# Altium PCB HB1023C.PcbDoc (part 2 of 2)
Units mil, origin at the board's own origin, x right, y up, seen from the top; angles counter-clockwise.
Board outline 1895.03 x 2760.94 mil, 2 copper layers (Top Layer, Bottom Layer); 83 components, 64 nets, 266 pads, 261 vias.
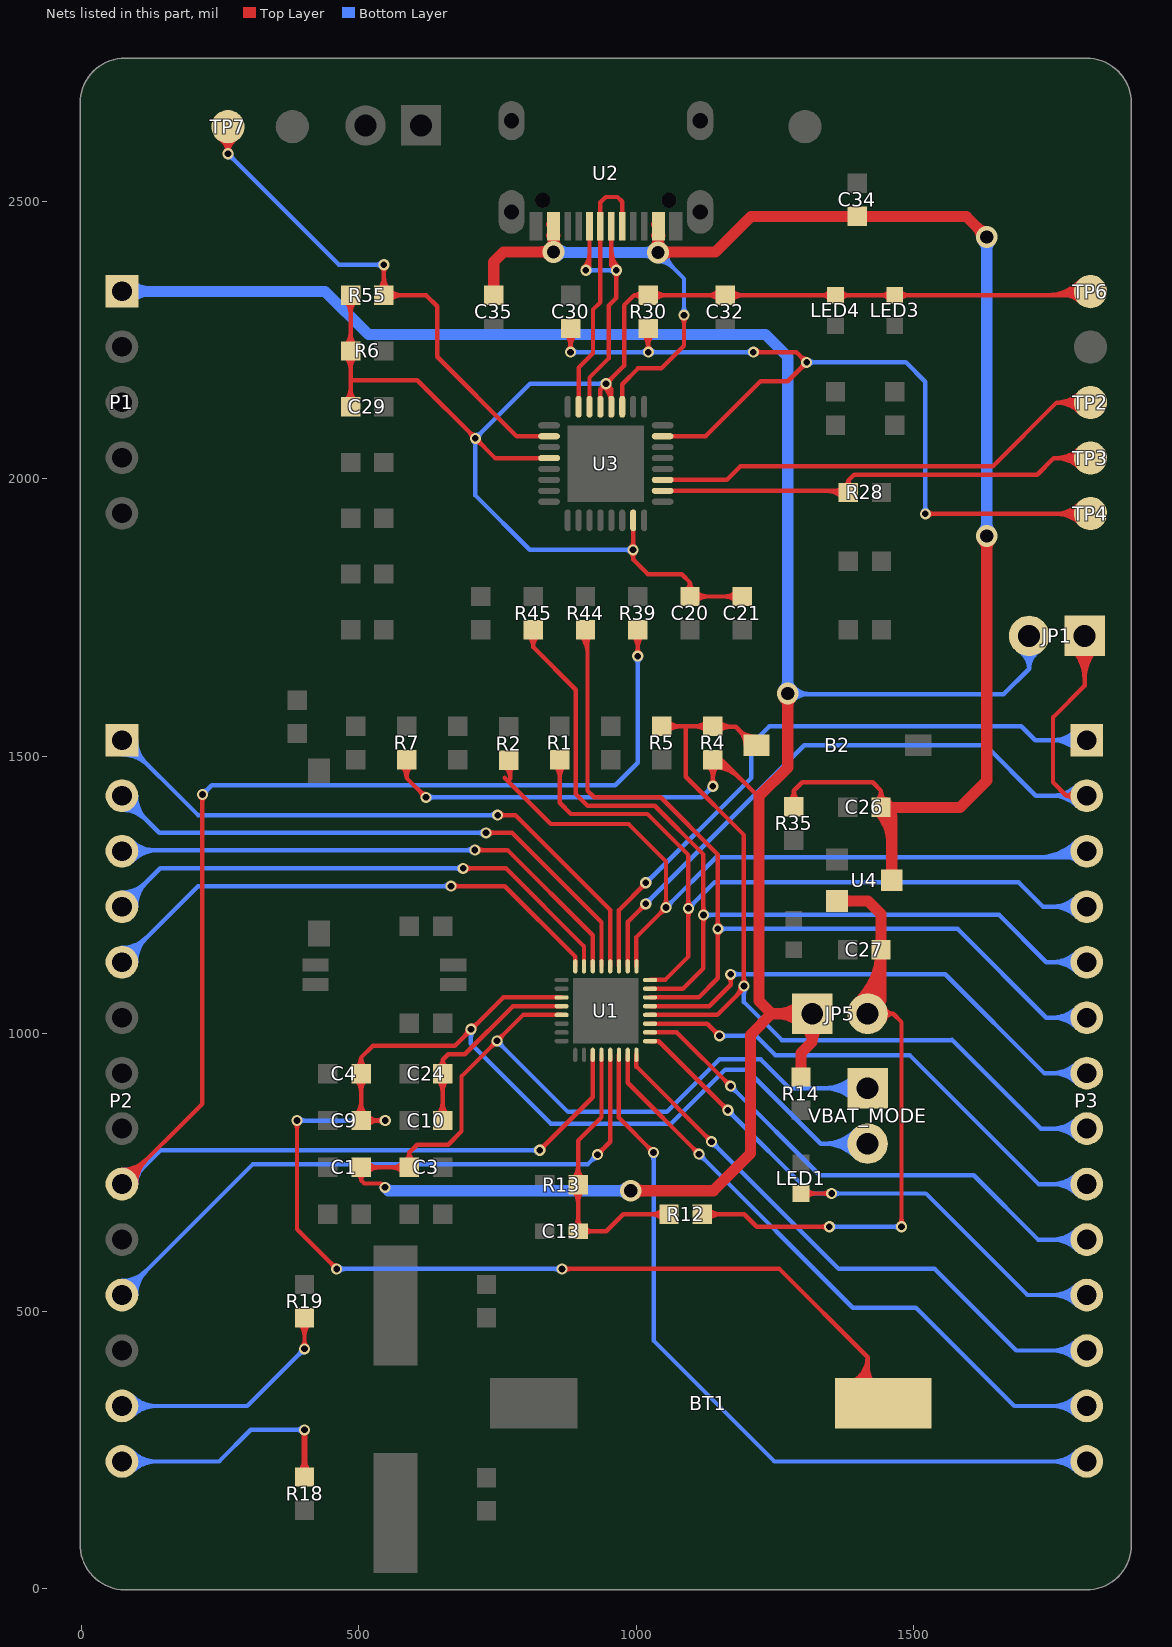
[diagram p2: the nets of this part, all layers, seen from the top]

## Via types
v1: diameter 20, hole 12, Top Layer to Bottom Layer, tented both sides, 243 vias
v2: diameter 39.37, hole 23.62, Top Layer to Bottom Layer, tented both sides, 10 vias
v3: diameter 122.05, hole 122.05, Top Layer to Bottom Layer, tented both sides, 4 vias
v4: diameter 25.98, hole 12.99, Top Layer to Bottom Layer, 4 vias

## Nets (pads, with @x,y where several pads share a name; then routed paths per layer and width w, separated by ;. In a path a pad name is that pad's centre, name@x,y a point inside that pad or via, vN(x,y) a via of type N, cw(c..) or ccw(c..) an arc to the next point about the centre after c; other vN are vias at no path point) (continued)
PA2: P2.9 R39.2 U1.11 | length 3334.6
  Top Layer w8: P2.9@73,729 218,874 v1@218,1430 ; P2.9@73,746.53 ccw(c73,788.84) 102.92,758.92 ccw(c132.84,729) P2.9@90.53,729 ; P2.9@73,754.53 ccw(c73,816.16) 116.58,772.58 ccw(c160.16,729) P2.9@98.53,729 ; v1@213.76,1426.76 cw(c203.51,1416.51) 218,1416.51 cw(c232.49,1416.51) v1@222.24,1426.76 ; v1(826,790) 921.5,885.5 U1.11@921.5,962 U1.11@921.5,961.19 ; v1@826,796 ccw(c826,810.49) 836.24,800.24 ccw(c846.49,790) v1@832,790 ; R39.2@993.05,1718.45 cw(c970.01,1695.41) 1002.6,1695.41 cw(c1035.19,1695.41) R39.2@1012.15,1718.45 ; v1@998.36,1684.64 ccw(c988.12,1694.89) 1002.6,1694.89 ccw(c1017.09,1694.89) v1@1006.84,1684.64 ; v1(1002.6,1680.4) R39.2@1002.6,1728
  Bottom Layer w8: P2.9@73,734 P2.9@73,729 81,729 142,790 v1(826,790) ; P2.9@73,738.53 ccw(c73,780.84) 102.92,750.92 ; P2.9@73,746.53 ccw(c73,808.16) 116.58,764.58 ; P2.9@73,754.53 ccw(c73,835.47) 130.23,778.23 ; P2.9@98.53,729 cw(c140.84,729) 110.92,758.92 ; v1(218,1431) 235,1448 962,1448 1002.6,1488.6 v1(1002.6,1680.4) v1@1002.2,1680 ; v1@218,1437 ccw(c218,1451.49) 228.24,1441.24 ccw(c238.49,1431) v1@224,1431 ; v1@821.76,785.76 ccw(c811.51,775.51) 811.51,790 ccw(c811.51,804.49) v1@821.76,794.24 ; v1@998.36,1676.16 cw(c988.12,1665.91) 1002.6,1665.91 cw(c1017.09,1665.91) v1@1006.84,1676.16
PA3: C13.2 R12.1 R13.1 U1.12 | length 739.9
  Top Layer w8: R13.1@885.45,718.45 cw(c862.41,695.41) 895,695.41 cw(c927.59,695.41) R13.1@904.55,718.45 ; R13.1@885.45,737.55 ccw(c862.41,760.59) 895,760.59 ccw(c927.59,760.59) R13.1@904.55,737.55 ; C13.2@888.08,650.92 ccw(c871.39,667.61) 895,667.61 ccw(c918.61,667.61) C13.2@901.92,650.92 ; C13.2@905.64,637.08 cw(c922.33,620.39) 922.33,644 cw(c922.33,667.61) C13.2@905.64,650.92 ; U1.12@937.25,962 937.25,849.25 895,807 C13.2@895,644 946,644 976.5,674.5 R12.1@1059,674.5 ; R12.1@1049.45,664.95 ccw(c1026.41,641.91) 1026.41,674.5 ccw(c1026.41,707.09) R12.1@1049.45,684.05
PA4: P2.11 U1.13 | length 1360.1
  Top Layer w8: v1(930,782) 953,805 U1.13@953,962 ; v1@930,788 ccw(c930,802.49) 940.24,792.24 ccw(c950.49,782) v1@936,782
  Bottom Layer w8: P2.11@73,529 309,765 913,765 v1(930,782) ; P2.11@73,546.53 ccw(c73,588.84) 102.92,558.92 ccw(c132.84,529) P2.11@90.53,529 ; P2.11@73,554.53 ccw(c73,616.16) 116.58,572.58 ccw(c160.16,529) P2.11@98.53,529 ; v1@924,782 cw(c909.51,782) 919.76,771.76 cw(c930,761.51) v1@930,776
PA6: P3.14 U1.14 | length 1620.9
  Top Layer w8: U1.14@968.75,962 968.75,848.31 v1(1031.06,786) ; v1@1025.06,786 ccw(c1010.57,786) 1020.82,796.24 ccw(c1031.06,806.48) v1@1031.06,792
  Bottom Layer w8: v1@1026.82,781.75 cw(c1016.57,771.51) 1031.06,771.51 cw(c1045.54,771.51) v1@1035.3,781.75 ; v1(1031.06,786) 1031.06,446.94 1249,229 P3.14@1812,229 ; P3.14@1793.95,210.95 ccw(c1750.37,167.37) 1750.37,229 ccw(c1750.37,290.63) P3.14@1793.95,247.05 ; P3.14@1799.61,216.61 ccw(c1769.69,186.68) 1769.69,229 ccw(c1769.69,271.32) P3.14@1799.61,241.39
PA7: P3.13 U1.15 | length 1328.1
  Top Layer w8: U1.15@984.5,962 984.5,911.5 v1(1113,783) ; v1@1107,783 ccw(c1092.51,783) 1102.76,793.24 ccw(c1113,803.49) v1@1113,789
  Bottom Layer w8: v1@1113,777 cw(c1113,762.51) 1123.24,772.76 cw(c1133.49,783) v1@1119,783 ; v1(1113,783) 1390,506 1504,506 1681,329 P3.13@1812,329 ; P3.13@1793.95,310.95 ccw(c1750.37,267.37) 1750.37,329 ccw(c1750.37,390.63) P3.13@1793.95,347.05 ; P3.13@1799.61,316.61 ccw(c1769.69,286.68) 1769.69,329 ccw(c1769.69,371.32) P3.13@1799.61,341.39
PA8: P3.10 U1.18 | length 1150.6
  Top Layer w8: U1.18@1024.85,1002.35 1073.15,1002.35 v1(1169.94,905.56) ; v1@1163.94,905.56 ccw(c1149.45,905.56) 1159.7,915.8 ccw(c1169.94,926.05) v1@1169.94,911.56
  Bottom Layer w8: v1@1169.94,899.56 cw(c1169.94,885.08) 1180.18,895.32 cw(c1190.42,905.56) v1@1175.94,905.56 ; v1(1169.94,905.56) 1330.5,745 1608,745 1724,629 P3.10@1812,629 ; P3.10@1793.95,610.95 ccw(c1750.37,567.37) 1750.37,629 ccw(c1750.37,690.63) P3.10@1793.95,647.05 ; P3.10@1799.61,616.61 ccw(c1769.69,586.68) 1769.69,629 ccw(c1769.69,671.32) P3.10@1799.61,641.39
PA9: P3.9 U1.19 | length 1115.7
  Top Layer w8: U1.19@1024.85,1018.1 1127.9,1018.1 v1(1150,996) ; v1@1144,996 ccw(c1129.51,996) 1139.76,1006.24 ccw(c1150,1016.49) v1@1150,1002
  Bottom Layer w8: v1(1150,996) 1216,996 1250.5,961.5 1492.5,961.5 1725,729 P3.9@1812,729 ; v1@1154.24,991.76 cw(c1164.49,981.51) 1164.49,996 cw(c1164.49,1010.49) v1@1154.24,1000.24 ; P3.9@1793.95,710.95 ccw(c1750.37,667.37) 1750.37,729 ccw(c1750.37,790.63) P3.9@1793.95,747.05 ; P3.9@1799.61,716.61 ccw(c1769.69,686.68) 1769.69,729 ccw(c1769.69,771.32) P3.9@1799.61,741.39
PA11: P3.6 R44.2 U1.22 | length 1967.7
  Top Layer w8: R44.2@898.85,1718.45 cw(c867.12,1686.72) 912,1686.72 ; R44.2@904.51,1724.11 cw(c886.43,1706.03) 912,1706.03 ; R44.2@908.4,1728 912,1724.4 912,1438 924,1426 1044,1426 1147,1323 v1(1147,1189) 1147,1100 1112.35,1065.35 U1.22@1024.85,1065.35 ; 912,1704.1 cw(c932.3,1704.1) R44.2@917.95,1718.45 ; v1@1142.76,1184.76 cw(c1132.51,1174.51) 1147,1174.51 cw(c1161.49,1174.51) v1@1151.24,1184.76 ; v1@1142.76,1193.24 ccw(c1132.51,1203.49) 1147,1203.49 ccw(c1161.49,1203.49) v1@1151.24,1193.24
  Bottom Layer w8: v1(1147,1189) 1579,1189 1739,1029 P3.6@1812,1029 ; v1@1151.24,1184.76 cw(c1161.49,1174.51) 1161.49,1189 cw(c1161.49,1203.49) v1@1151.24,1193.24 ; P3.6@1793.95,1010.95 ccw(c1750.37,967.37) 1750.37,1029 ccw(c1750.37,1090.63) P3.6@1793.95,1047.05 ; P3.6@1799.61,1016.61 ccw(c1769.69,986.68) 1769.69,1029 ccw(c1769.69,1071.32) P3.6@1799.61,1041.39
PA12: P3.5 R45.2 U1.23 | length 1925
  Top Layer w8: R45.2@804.96,1718.16 cw(c784.9,1696.8) 814.2,1696.8 ; R45.2@814.2,1728 814.2,1696.8 ; R45.2@823.44,1718.16 ccw(c843.5,1696.8) 814.2,1696.8 ; U1.23@1024.85,1081.09 1084.09,1081.09 1121,1118 v1(1121,1214) 1121,1323 1033,1411 912,1411 891,1432 891,1620 814.2,1696.8 ; v1@1116.76,1209.76 cw(c1106.51,1199.51) 1121,1199.51 cw(c1135.49,1199.51) v1@1125.24,1209.76 ; v1@1116.76,1218.24 ccw(c1106.51,1228.49) 1121,1228.49 ccw(c1135.49,1228.49) v1@1125.24,1218.24
  Bottom Layer w8: v1(1121,1214) 1654,1214 1739,1129 P3.5@1812,1129 ; v1@1125.24,1209.76 cw(c1135.49,1199.51) 1135.49,1214 cw(c1135.49,1228.49) v1@1125.24,1218.24 ; P3.5@1793.95,1110.95 ccw(c1750.37,1067.37) 1750.37,1129 ccw(c1750.37,1190.63) P3.5@1793.95,1147.05 ; P3.5@1799.61,1116.61 ccw(c1769.69,1086.68) 1769.69,1129 ccw(c1769.69,1171.32) P3.5@1799.61,1141.39
PA13: P3.4 R1.1 U1.24 | length 1657
  Top Layer w8: R1.1@852.45,1484.45 cw(c829.41,1461.41) 862,1461.41 cw(c894.59,1461.41) R1.1@871.55,1484.45 ; R1.1@862,1494 862,1416 882,1396 1020,1396 1094,1322 v1(1094,1226) 1094,1139 1051.84,1096.84 U1.24@1024.85,1096.84 ; v1@1089.76,1221.76 cw(c1079.51,1211.51) 1094,1211.51 cw(c1108.49,1211.51) v1@1098.24,1221.76 ; v1@1089.76,1230.24 ccw(c1079.51,1240.49) 1094,1240.49 ccw(c1108.49,1240.49) v1@1098.24,1230.24
  Bottom Layer w8: v1(1094,1226) 1141,1273 1689,1273 1733,1229 P3.4@1812,1229 ; v1@1094,1232 ccw(c1094,1246.49) 1104.24,1236.24 ccw(c1114.49,1226) v1@1100,1226 ; P3.4@1793.95,1210.95 ccw(c1750.37,1167.37) 1750.37,1229 ccw(c1750.37,1290.63) P3.4@1793.95,1247.05 ; P3.4@1799.61,1216.61 ccw(c1769.69,1186.68) 1769.69,1229 ccw(c1769.69,1271.32) P3.4@1799.61,1241.39
PA14: P3.3 R2.1 U1.25 | length 1748.7
  Top Layer w8: R2.1@761.86,1482.23 cw(c744.98,1459.87) 773,1459.87 ; 763,1461 846,1378 986,1378 1053.5,1310.5 v1(1053.5,1227.5) 1000.24,1174.24 U1.25@1000.24,1121.45 ; 773,1460 R2.1@773,1493 ; 773,1467.65 cw(c795.35,1467.65) R2.1@779.55,1483.45 ; v1@1047.5,1227.5 cw(c1033.01,1227.5) 1043.26,1217.26 cw(c1053.5,1207.01) v1@1053.5,1221.5 ; v1@1049.26,1231.74 ccw(c1039.01,1241.99) 1053.5,1241.99 ccw(c1067.99,1241.99) v1@1057.74,1231.74
  Bottom Layer w8: v1(1053.5,1227.5) 1144,1318 1801,1318 P3.3@1812,1329 ; v1@1053.5,1233.5 ccw(c1053.5,1247.99) 1063.74,1237.74 ccw(c1073.99,1227.5) v1@1059.5,1227.5 ; 1723.82,1318 ccw(c1723.82,1417.19) P3.3@1793.95,1347.05 ; 1743.13,1318 ccw(c1743.13,1397.87) P3.3@1799.61,1341.39 ; 1762.44,1318 ccw(c1762.44,1378.56) P3.3@1805.26,1335.74 ; 1776.93,1318 cw(c1776.93,1293.93) P3.3@1793.95,1310.95 ; 1781.76,1318 ccw(c1781.76,1359.24) P3.3@1810.92,1330.08
PB0: P3.12 U1.16 | length 1253.8
  Top Layer w8: U1.16@1000.24,962 1000.24,940.76 v1(1135.59,805.41) ; v1@1129.59,805.41 ccw(c1115.11,805.41) 1125.35,815.65 ccw(c1135.59,825.89) v1@1135.59,811.41
  Bottom Layer w8: v1@1135.59,799.41 cw(c1135.59,784.92) 1145.83,795.17 cw(c1156.08,805.41) v1@1141.59,805.41 ; v1(1135.59,805.41) 1365,576 1538,576 1685,429 P3.12@1812,429 ; P3.12@1793.95,410.95 ccw(c1750.37,367.37) 1750.37,429 ccw(c1750.37,490.63) P3.12@1793.95,447.05 ; P3.12@1799.61,416.61 ccw(c1769.69,386.68) 1769.69,429 ccw(c1769.69,471.32) P3.12@1799.61,441.39
PB3: P2.2 U1.29 | length 1246.9
  Top Layer w8: v1(729,1362) 776,1362 937.25,1200.75 U1.29@937.25,1121.45 ; v1@733.24,1357.76 cw(c743.49,1347.51) 743.49,1362 cw(c743.49,1376.49) v1@733.24,1366.24
  Bottom Layer w8: P2.2@73,1403.47 cw(c73,1341.84) 116.58,1385.42 cw(c160.16,1429) P2.2@98.53,1429 ; P2.2@73,1411.47 cw(c73,1369.16) 102.92,1399.08 cw(c132.84,1429) P2.2@90.53,1429 ; P2.2@73,1429 140,1362 v1(729,1362) ; v1@724.76,1357.76 ccw(c714.51,1347.51) 714.51,1362 ccw(c714.51,1376.49) v1@724.76,1366.24
PB4: P2.3 U1.30 | length 1177.7
  Top Layer w8: v1(709,1331) 768,1331 921.5,1177.5 U1.30@921.5,1121.45 ; v1@713.24,1326.76 cw(c723.49,1316.51) 723.49,1331 cw(c723.49,1345.49) v1@713.24,1335.24
  Bottom Layer w8: P2.3@73,1329 75,1331 v1(709,1331) ; P2.3@85.39,1316.61 cw(c120.14,1281.86) 120.14,1331 ; P2.3@85.39,1341.39 ccw(c110.49,1366.49) 110.49,1331 ; P2.3@91.05,1310.95 cw(c139.46,1262.54) 139.46,1331 ; P2.3@91.05,1347.05 ccw(c129.8,1385.8) 129.8,1331 ; v1@704.76,1326.76 ccw(c694.51,1316.51) 694.51,1331 ccw(c694.51,1345.49) v1@704.76,1335.24
PB6: P2.4 U1.31 | length 1164.2
  Top Layer w8: v1(688,1298) 765,1298 905.76,1157.24 U1.31@905.76,1121.45 ; v1@692.24,1293.76 cw(c702.49,1283.51) 702.49,1298 cw(c702.49,1312.49) v1@692.24,1302.24
  Bottom Layer w8: P2.4@73,1229 142,1298 v1(688,1298) ; P2.4@73,1246.53 ccw(c73,1288.84) 102.92,1258.92 ccw(c132.84,1229) P2.4@90.53,1229 ; P2.4@73,1254.53 ccw(c73,1316.16) 116.58,1272.58 ccw(c160.16,1229) P2.4@98.53,1229 ; v1@683.76,1293.76 ccw(c673.51,1283.51) 673.51,1298 ccw(c673.51,1312.49) v1@683.76,1302.24
PB7: P2.5 U1.32 | length 1152.7
  Top Layer w8: v1(666,1266) 763,1266 890.01,1138.99 U1.32@890.01,1121.45 ; v1@670.24,1261.76 cw(c680.49,1251.51) 680.49,1266 cw(c680.49,1280.49) v1@670.24,1270.24
  Bottom Layer w8: P2.5@73,1129 210,1266 v1(666,1266) ; P2.5@73,1146.53 ccw(c73,1188.84) 102.92,1158.92 ccw(c132.84,1129) P2.5@90.53,1129 ; P2.5@73,1154.53 ccw(c73,1216.16) 116.58,1172.58 ccw(c160.16,1129) P2.5@98.53,1129 ; v1@661.76,1261.76 ccw(c651.51,1251.51) 651.51,1266 ccw(c651.51,1280.49) v1@661.76,1270.24
PB14: LED1.2 P3.11 U1.17 | length 1376.6
  Top Layer w8: U1.17@1024.85,986.61 1040.39,986.61 v1(1165,862) ; U1.17@1033.7,986.67 cw(c1035.27,974.8) 1043.74,983.26 ; U1.17@1033.71,986.67 cw(c1033.71,970.68) 1045.01,981.99 ; v1@1159,862 ccw(c1144.51,862) 1154.76,872.24 ccw(c1165,882.49) v1@1165,868 ; LED1.2@1296,710.78 1297.22,712 v1(1352,712) ; LED1.2@1296.78,712 LED1.2@1298,710.78 ; LED1.2@1304.56,704.22 cw(c1323.34,685.44) 1323.34,712 cw(c1323.34,738.56) LED1.2@1304.56,719.78 ; v1@1347.76,707.76 ccw(c1337.51,697.51) 1337.51,712 ccw(c1337.51,726.49) v1@1347.76,716.24
  Bottom Layer w8: v1@1165,856 cw(c1165,841.51) 1175.24,851.76 cw(c1185.49,862) v1@1171,862 ; v1(1165,862) 1315,712 v1(1352,712) ; v1@1347.76,707.76 ccw(c1337.51,697.51) 1337.51,712 ccw(c1337.51,726.49) v1@1347.76,716.24 ; v1@1353,713 1354,712 1522,712 1705,529 P3.11@1812,529 ; v1@1356.24,707.76 cw(c1366.49,697.51) 1366.49,712 cw(c1366.49,726.49) v1@1356.24,716.24 ; P3.11@1793.95,510.95 ccw(c1750.37,467.37) 1750.37,529 ccw(c1750.37,590.63) P3.11@1793.95,547.05 ; P3.11@1799.61,516.61 ccw(c1769.69,486.68) 1769.69,529 ccw(c1769.69,571.32) P3.11@1799.61,541.39
PC7: B2.2 P3.8 R4.1 R5.2 U1.20 | length 2087.9
  Top Layer w8: U1.20@1024.85,1033.85 1145.85,1033.85 v1@1194,1082 ; R5.2@1044,1554 R4.1@1138,1554 ; R5.2@1055.55,1544.45 cw(c1078.59,1521.41) 1078.59,1554 cw(c1078.59,1586.59) R5.2@1055.55,1563.55 ; 1089,1553 1089,1463 1194,1358 v1(1194,1086) ; R4.1@1128.45,1544.45 ccw(c1105.41,1521.41) 1105.41,1554 ccw(c1105.41,1586.59) R4.1@1128.45,1563.55 ; R4.1@1138,1543 1148,1553 1179,1553 1212.06,1519.94 B2.2@1216.66,1519.94 ; R4.1@1147.55,1544.45 cw(c1168.18,1523.82) 1168.18,1553 ; R4.1@1147.55,1563.55 ccw(c1173.01,1589.01) 1173.01,1553 ; 1180.93,1068.93 ccw(c1163.86,1086) v1@1188,1086 ; 1184.81,1547.19 ccw(c1212.72,1575.11) B2.2@1212.72,1535.63 ; 1186.42,1545.58 cw(c1160.79,1519.94) B2.2@1197.04,1519.94 ; v1@1189.76,1090.24 ccw(c1179.51,1100.49) 1194,1100.49 ccw(c1208.49,1100.49) v1@1198.24,1090.24 ; B2.2@1198.46,1533.54 ccw(c1212.72,1547.8) B2.2@1212.72,1527.63
  Bottom Layer w8: v1@1189.76,1081.76 cw(c1179.51,1071.51) 1194,1071.51 cw(c1208.49,1071.51) v1@1198.24,1081.76 ; v1(1194,1086) 1194,1057 1262.42,988.58 1568.58,988.58 ; 1569,989 1729,829 P3.8@1812,829 ; P3.8@1793.95,810.95 ccw(c1750.37,767.37) 1750.37,829 ccw(c1750.37,890.63) P3.8@1793.95,847.05 ; P3.8@1799.61,816.61 ccw(c1769.69,786.68) 1769.69,829 ccw(c1769.69,871.32) P3.8@1799.61,841.39
PC8: P3.7 U1.21 | length 1104.6
  Top Layer w8: U1.21@1024.85,1049.6 1131.6,1049.6 1170,1088 v1(1170,1107) ; v1@1165.76,1102.76 cw(c1155.51,1092.51) 1170,1092.51 cw(c1184.49,1092.51) v1@1174.24,1102.76
  Bottom Layer w8: v1(1170,1107) 1557,1107 1735,929 P3.7@1812,929 ; v1@1174.24,1102.76 cw(c1184.49,1092.51) 1184.49,1107 cw(c1184.49,1121.49) v1@1174.24,1111.24 ; P3.7@1793.95,910.95 ccw(c1750.37,867.37) 1750.37,929 ccw(c1750.37,990.63) P3.7@1793.95,947.05 ; P3.7@1799.61,916.61 ccw(c1769.69,886.68) 1769.69,929 ccw(c1769.69,971.32) P3.7@1799.61,941.39
PC9: JP1.1 P3.2 U1.26 | length 1960.1
  Top Layer w8: U1.26@984.5,1121.45 984.5,1201.5 v1@1015,1232 ; v1@1011,1234 cw(c996.51,1234) 1006.76,1223.76 cw(c1017,1213.51) v1@1017,1228 ; v1@1017,1232 v1@1015,1232 ; v1(1017,1234) v1@1015,1232 ; JP1.1@1785.08,1694.08 cw(c1729.74,1638.74) 1808,1638.74 cw(c1886.26,1638.74) JP1.1@1830.92,1694.08 ; P3.2@1788.14,1419.94 ccw(c1775,1414.95) 1775,1429 ; P3.2@1788.14,1438.06 cw(c1775,1443.05) 1775,1429 ; JP1.1@1790.73,1699.73 cw(c1749.05,1658.05) 1808,1658.05 cw(c1866.95,1658.05) JP1.1@1825.27,1699.73 ; JP1.1@1796.39,1705.39 cw(c1768.37,1677.37) 1808,1677.37 cw(c1847.64,1677.37) JP1.1@1819.61,1705.39 ; JP1.1@1808,1717 1808,1627 1751,1570 1751,1453 1775,1429 ; P3.2@1812,1429 1775,1429
  Bottom Layer w8: v1(1017,1234) 1302.78,1519.78 1629.22,1519.78 1720,1429 P3.2@1812,1429 P3.2@1814,1429 ; v1@1017,1240 ccw(c1017,1254.49) 1027.24,1244.24 ccw(c1037.49,1234) v1@1023,1234 ; P3.2@1793.95,1410.95 ccw(c1750.37,1367.37) 1750.37,1429 ccw(c1750.37,1490.63) P3.2@1793.95,1447.05 ; P3.2@1799.61,1416.61 ccw(c1769.69,1386.68) 1769.69,1429 ccw(c1769.69,1471.32) P3.2@1799.61,1441.39
PC10: P3.1 U1.27 | length 1334.6
  Top Layer w8: U1.27@968.75,1121.45 968.75,1222.75 v1@1017,1271 ; 1006.05,1260.05 ccw(c994.1,1272) v1@1011,1272 ; 1008.46,1262.46 cw(c1017,1253.93) v1@1017,1266
  Bottom Layer w8: v1@1017,1278 ccw(c1017,1294.9) 1028.95,1282.95 ; v1@1018,1272 1207,1461 1207,1521 1240,1554 1694,1554 1719,1529 P3.1@1812,1529 ; v1@1023,1272 cw(c1035.07,1272) 1026.54,1280.54 ; P3.1@1793.95,1510.95 ccw(c1750.37,1467.37) 1750.37,1529 ccw(c1750.37,1590.63) P3.1@1793.95,1547.05 ; P3.1@1799.61,1516.61 ccw(c1769.69,1486.68) 1769.69,1529 ccw(c1769.69,1571.32) P3.1@1799.61,1541.39
  other v1: 1017,1272
PC11: P2.1 U1.28 | length 1317.1
  Top Layer w8: v1(750,1394) 782,1394 953,1223 U1.28@953,1121.45 ; v1@754.24,1389.76 cw(c764.49,1379.51) 764.49,1394 cw(c764.49,1408.49) v1@754.24,1398.24
  Bottom Layer w8: P2.1@73,1503.47 cw(c73,1437.02) 119.99,1484.01 ; P2.1@73,1511.47 cw(c73,1464.33) 106.34,1497.66 ; P2.1@73,1529 75,1529 210,1394 v1(750,1394) ; P2.1@90.53,1529 ccw(c128.02,1529) P2.1@101.51,1502.49 ; P2.1@98.53,1529 ccw(c155.33,1529) 115.16,1488.84 ; v1@745.76,1389.76 ccw(c735.51,1379.51) 735.51,1394 ccw(c735.51,1408.49) v1@745.76,1398.24
PF0: P2.13 R19.2 | length 687.6
  Top Layer w8: R19.2@392.45,478.45 cw(c369.41,455.41) 402,455.41 cw(c434.59,455.41) R19.2@411.55,478.45 ; v1@397.76,436.24 ccw(c387.51,446.49) 402,446.49 ccw(c416.48,446.49) v1@406.24,436.24 ; v1(402,432) R19.2@402,488
  Bottom Layer w8: P2.13@73,329 299,329 v1(402,432) ; P2.13@85.39,316.61 cw(c115.32,286.68) 115.32,329 cw(c115.32,371.32) P2.13@85.39,341.39 ; P2.13@91.05,310.95 cw(c134.63,267.37) 134.63,329 cw(c134.63,390.63) P2.13@91.05,347.05 ; v1@396,432 cw(c381.51,432) 391.76,421.76 cw(c402,411.52) v1@402,426
PF1: P2.14 R18.2 | length 690
  Top Layer w10: R18.2@393.16,209.84 ccw(c371.82,231.18) 402,231.18 ccw(c432.18,231.18) R18.2@410.84,209.84 ; v1@398.46,282.46 cw(c389.93,273.93) 402,273.93 cw(c414.07,273.93) v1@405.54,282.46 ; R18.2@402,201 v1(402,286)
  Bottom Layer w8: P2.14@73,229 248,229 305,286 v1(402,286) ; P2.14@85.39,216.61 cw(c115.32,186.68) 115.32,229 cw(c115.32,271.32) P2.14@85.39,241.39 ; P2.14@91.05,210.95 cw(c134.63,167.37) 134.63,229 cw(c134.63,290.63) P2.14@91.05,247.05 ; v1@397.76,281.76 ccw(c387.51,271.51) 387.51,286 ccw(c387.51,300.49) v1@397.76,290.24
PRG_NRST: C30.1 R30.2 TP4.1 U3.7 | length 2139.7
  Top Layer w8: C30.1@872.62,2261.45 cw(c851.18,2240.02) 881.5,2240.02 ; v1@877.26,2232.74 ccw(c867.02,2242.99) 881.5,2242.99 ccw(c895.99,2242.99) v1@885.74,2232.74 ; v1(881.5,2228.5) 881.5,2270.33 C30.1@882.17,2271 ; v1@881.5,2236.8 cw(c916.37,2236.8) C30.1@891.71,2261.45 ; R30.2@1011.79,2261.45 cw(c988.74,2238.41) 1021.33,2238.41 cw(c1053.92,2238.41) R30.2@1030.88,2261.45 ; v1@1017.56,2232.74 ccw(c1008.45,2241.85) 1021.33,2241.85 ; 1021.33,2244.12 ccw(c1037.42,2244.12) v1@1026.04,2232.74 ; R30.2@1021.33,2271 1021.33,2228.97 v1(1021.8,2228.5) ; U3.7@1047.52,2076.85 1124.85,2076.85 1224,2176 1273,2176 v1(1307,2210) 1288.5,2228.5 v1(1211,2228.5) ; v1@1215.24,2224.26 cw(c1225.49,2214.01) 1225.49,2228.5 cw(c1225.49,2242.99) v1@1215.24,2232.74 ; v1@1307,2204 ccw(c1307,2189.51) 1296.76,2199.76 ccw(c1286.51,2210) 1301,2210 ccw(c1286.51,2210) 1296.76,2220.24 ccw(c1307,2230.49) v1@1307,2216 ; v1(1521,1937) 1817.94,1937 TP4.1@1818.45,1937.5 ; v1@1525.24,1932.76 cw(c1535.49,1922.51) 1535.49,1937 cw(c1535.49,1951.49) v1@1525.24,1941.24 ; 1754.46,1937 ccw(c1754.46,2001.49) TP4.1@1800.06,1955.89 ; 1756.9,1937 cw(c1756.9,1875.95) TP4.1@1800.06,1919.12 ; 1773.78,1937 ccw(c1773.78,1982.18) TP4.1@1805.72,1950.23 ; 1776.21,1937 cw(c1776.21,1895.26) TP4.1@1805.72,1924.78
  Bottom Layer w8: v1(881.5,2228.5) v1(1021.8,2228.5) v1(1211,2228.5) ; v1@885.74,2224.26 cw(c895.99,2214.01) 895.99,2228.5 cw(c895.99,2242.99) v1@885.74,2232.74 ; v1@1017.56,2224.26 ccw(c1007.32,2214.01) 1007.32,2228.5 ccw(c1007.32,2242.99) v1@1017.56,2232.74 ; v1@1026.04,2224.26 cw(c1036.29,2214.01) 1036.29,2228.5 cw(c1036.29,2242.99) v1@1026.04,2232.74 ; v1@1206.76,2224.26 ccw(c1196.51,2214.01) 1196.51,2228.5 ccw(c1196.51,2242.99) v1@1206.76,2232.74 ; v1(1307,2210) 1486,2210 1521,2175 v1(1521,1937) ; v1@1311.24,2205.76 cw(c1321.49,2195.51) 1321.49,2210 cw(c1321.49,2224.49) v1@1311.24,2214.24 ; v1@1516.76,1941.24 ccw(c1506.51,1951.49) 1521,1951.49 ccw(c1535.49,1951.49) v1@1525.24,1941.24
PRG_SWCLK: R28.2 TP3.1 U3.2 | length 1070
  Top Layer w8: U3.2@1047.52,1978.43 1379.07,1978.43 R28.2@1382,1975.5 1382,1997 ; 1342.34,1978.43 cw(c1342.34,1935.84) R28.2@1372.45,1965.95 ; 1356.47,1978.43 ccw(c1356.47,2001.03) R28.2@1372.45,1985.05 ; 1361.66,1978.43 cw(c1361.66,1955.16) R28.2@1378.11,1971.61 ; R28.2@1376.14,1987.66 ccw(c1371.63,1997) 1382,1997 ; R28.2@1387.87,1987.66 cw(c1392.37,1997) 1382,1997 ; TP3.1@1800.06,2019.12 ccw(c1755.68,1974.73) 1755.68,2037.5 ccw(c1755.68,2100.27) TP3.1@1800.06,2055.89 ; TP3.1@1805.72,2024.78 ccw(c1774.99,1994.05) 1774.99,2037.5 ccw(c1774.99,2080.96) TP3.1@1805.72,2050.23 ; TP3.1@1818.45,2037.5 1752.5,2037.5 1722.48,2007.48 1392.48,2007.48 1382,1997
PRG_SWDIO: TP2.1 U3.3 | length 988.4
  Top Layer w8: U3.3@1047.63,1998 U3.3@1047.52,1998.11 1162.89,1998.11 1163,1998 1187.48,2022.48 1642.48,2022.48 1757.5,2137.5 TP2.1@1818.45,2137.5 ; TP2.1@1799.68,2119.51 ccw(c1757.51,2079.08) 1757.51,2137.5 ccw(c1757.51,2195.92) TP2.1@1799.68,2155.5 ; TP2.1@1805.45,2125.05 ccw(c1776.26,2097.06) 1776.26,2137.5 ccw(c1776.26,2177.95) TP2.1@1805.45,2149.96
UPDATE_CTRL: R55.2 TP7.1 U3.18 | length 1235
  Top Layer w8: TP7.1@249.51,2613.19 cw(c231.25,2586) v1(264,2586) ; TP7.1@253.97,2619.84 cw(c241.32,2601.01) 264,2601.01 cw(c286.68,2601.01) TP7.1@274.03,2619.84 ; v1@259.76,2590.24 ccw(c249.51,2600.49) 264,2600.49 ccw(c278.49,2600.49) v1@268.24,2590.24 ; TP7.1@264,2634.78 v1(264,2586) ; TP7.1@278.49,2613.19 ccw(c296.75,2586) v1(264,2586) ; R55.2@535.45,2340.55 ccw(c512.41,2363.59) 545,2363.59 ccw(c577.59,2363.59) 554.55,2340.55 ccw(c577.59,2363.59) 577.59,2331 ccw(c577.59,2298.41) R55.2@554.55,2321.45 ; v1@540.76,2381.76 cw(c530.51,2371.51) 545,2371.51 cw(c559.48,2371.52) v1@549.24,2381.76 ; R55.2@545,2340 R55.2@545,2331 ; v1(545,2386) R55.2@545,2331 ; U3.18@842.8,2076.85 784.15,2076.85 641,2220 641,2311 621,2331 R55.2@545,2331
  Bottom Layer w8: v1@264,2580 cw(c264,2565.51) 274.24,2575.76 cw(c284.49,2586) v1@270,2586 ; v1(264,2586) 464,2386 v1(545,2386) ; v1@540.76,2381.76 ccw(c530.51,2371.51) 530.51,2386 ccw(c530.51,2400.49) v1@540.76,2390.24
USB_DM: U2.A7 U2.B7 U3.15 | length 475.5
  Top Layer w8: U3.15@895.94,2130 896,2130.06 896,2200.21 922,2226.21 922,2305.21 935.33,2318.55 U2.A7@935.33,2455.46 935.33,2498.33 945,2508 966,2508 974.7,2499.3 U2.B7@974.7,2455.46
USB_DP: U2.A6 U2.B6 U3.14 | length 654.2
  Top Layer w8: v1@904.76,2380.24 ccw(c878.47,2406.53) 915.64,2406.53 ; v1(909,2376) 915.64,2382.64 U2.B6@915.64,2455.46 ; v1@910.41,2374.59 ccw(c897.79,2387.21) 915.64,2387.21 ; U3.14@916,2130.37 U3.14@915.63,2130 915.63,2182.63 950,2217 950,2312 964,2326 v1(964,2376) 955.01,2384.99 U2.A6@955.01,2455.46 ; 955.01,2392.86 ccw(c980.87,2392.86) v1@962.59,2374.59 ; 955.01,2412.18 ccw(c1000.18,2412.18) v1@968.24,2380.24 ; v1@959.76,2371.76 cw(c949.51,2361.51) 964,2361.51 cw(c978.49,2361.51) v1@968.24,2371.76
  Bottom Layer w8: v1(909,2376) v1(964,2376) ; v1@913.24,2371.76 cw(c923.49,2361.51) 923.49,2376 cw(c923.49,2390.49) v1@913.24,2380.24 ; v1@959.76,2371.76 ccw(c949.51,2361.51) 949.51,2376 ccw(c949.51,2390.49) v1@959.76,2380.24
VBAT: BT1.1 C4.2 C9.2 U1.3 VBAT_MODE.2 | length 3976.4
  Top Layer w8: v1@384.26,839.26 cw(c374.01,829.01) 388.5,829.01 cw(c402.99,829.01) v1@392.74,839.26 ; v1(388.5,843.5) 388.5,647.5 v1(460,576) ; v1@454,576 ccw(c439.51,576) 449.76,586.24 ccw(c460,596.49) v1@460,582 ; C9.2@494.45,853.05 ccw(c471.41,876.09) 504,876.09 ccw(c536.59,876.09) 513.55,853.05 ccw(c536.59,876.09) 536.59,843.5 ccw(c536.59,810.91) C9.2@513.55,833.95 ; C4.2@494.45,918.45 cw(c471.41,895.41) 504,895.41 cw(c536.59,895.41) C4.2@513.55,918.45 ; C4.2@495.31,938.33 ccw(c479.6,957) 504,957 ; C4.2@512.69,938.33 cw(c528.4,957) 504,957 ; v1@543.26,839.26 ccw(c533.01,829.01) 533.01,843.5 ccw(c533.01,857.99) v1@543.26,847.74 ; v1(547.5,843.5) C9.2@504,843.5 C4.2@504,928 504,957 ; 691.05,996.05 ccw(c679.1,1008) v1@696,1008 ; 693.46,998.46 cw(c702,989.93) v1@702,1002 ; v1@702,1014 ccw(c702,1030.9) 713.95,1018.95 ; v1@708,1008 cw(c720.07,1008) 711.54,1016.54 ; U1.3@865.4,1065.35 760.35,1065.35 673,978 525,978 504,957 ; v1(866,576) 1258,576 1417,417 ; v1@870.24,571.76 cw(c880.49,561.51) 880.49,576 cw(c880.49,590.49) v1@870.24,580.24 ; BT1.1@1387.35,371.89 ccw(c1367.87,417) 1417,417 ; BT1.1@1390.52,364.55 ccw(c1373.13,404.83) 1417,404.83 ; BT1.1@1393.69,357.2 ccw(c1378.38,392.66) 1417,392.66 ; BT1.1@1396.86,349.86 ccw(c1383.63,380.49) 1417,380.49 ; BT1.1@1417,379.05 1417,417 ; 1417,382.25 ccw(c1451.95,382.25) BT1.1@1427.24,357.53 ; 1417,401.56 ccw(c1471.27,401.56) BT1.1@1432.89,363.19 ; BT1.1@1431,334 BT1.1@1445.05,334
  Bottom Layer w8: v1(388.5,843.5) v1(547.5,843.5) ; v1@392.74,839.26 cw(c402.99,829.01) 402.99,843.5 cw(c402.99,857.99) v1@392.74,847.74 ; v1(460,576) v1(866,576) ; v1@464.24,571.76 cw(c474.49,561.51) 474.49,576 cw(c474.49,590.49) v1@464.24,580.24 ; v1@543.26,839.26 ccw(c533.01,829.01) 533.01,843.5 ccw(c533.01,857.99) v1@543.26,847.74 ; v1@697.76,1003.76 cw(c687.51,993.51) 702,993.51 cw(c716.49,993.51) v1@706.24,1003.76 ; v1(702,1008) 702,982 846,838 1063,838 1160,935 1199,935 1332.22,801.78 VBAT_MODE.2@1417,801.78 ; v1@861.76,571.76 ccw(c851.51,561.51) 851.51,576 ccw(c851.51,590.49) v1@861.76,580.24 ; VBAT_MODE.2@1394.08,778.86 ccw(c1338.74,723.52) 1338.74,801.78 ccw(c1338.74,880.04) VBAT_MODE.2@1394.08,824.7 ; VBAT_MODE.2@1399.73,784.51 ccw(c1358.05,742.83) 1358.05,801.78 ccw(c1358.05,860.73) VBAT_MODE.2@1399.73,819.04 ; VBAT_MODE.2@1405.39,790.17 ccw(c1377.37,762.14) 1377.37,801.78 ccw(c1377.37,841.41) VBAT_MODE.2@1405.39,813.39
VBUS_5V: C26.2 C34.2 C35.1 R35.2 U2.A4 U2.A9 U2.B4 U2.B9 U3.11 U4.3 | length 3921.5
  Top Layer w8: U2.A9@844.77,2455.47 U2.A9@845,2455.24 ; U3.11@974.68,2130 974.68,2170.68 1003,2199 1045,2199 1086,2240 v1(1086,2295) ; v1@1081.76,2290.76 cw(c1071.51,2280.51) 1086,2280.51 cw(c1100.49,2280.51) v1@1090.24,2290.76 ; R35.2@1275.31,1419.33 ccw(c1259.6,1438) 1284,1438 ; R35.2@1284,1409 1284,1438 ; R35.2@1292.69,1419.33 cw(c1308.4,1438) 1284,1438 ; C34.2@1397,2474 C34.2@1398,2473 ; C26.2@1432.05,1418.1 ccw(c1414.42,1438) 1441,1438 ; C26.2@1441,1408 1441,1438 ; C26.2@1449.95,1418.1 cw(c1467.58,1438) 1441,1438 ; 1284,1438 1299,1453 1426,1453 1441,1438
  Top Layer w20: C35.1@737.7,2336.3 ccw(c724.89,2349.11) 743,2349.11 ccw(c761.11,2349.11) C35.1@748.3,2336.3 ; C35.1@743,2331 743,2391 761,2409 v2(851,2409) U2.B4@851,2455.47 ; v2@844.15,2402.15 ccw(c827.62,2385.62) 827.62,2409 ccw(c827.62,2432.38) 844.15,2415.85 ccw(c827.62,2432.38) 851,2432.38 ccw(c874.38,2432.38) v2@857.85,2415.85 ; U2.A9@847.67,2438.68 cw(c839.63,2430.64) U2.B4@851,2430.64 ; U2.A9@847.67,2458.36 cw(c839.63,2450.32) U2.B4@851,2450.32 ; U2.B4@851,2432.16 cw(c860.22,2432.16) U2.B4@853.7,2438.68 ; v2@1032.15,2414.85 ccw(c1013.8,2433.2) U2.A4@1039.75,2433.2 ; U2.B9@1036.65,2438.67 cw(c1029.15,2431.17) U2.A4@1039.75,2431.17 ; U2.B9@1036.65,2458.35 cw(c1029.15,2450.86) U2.A4@1039.75,2450.86 ; v2@1039.75,2413.75 U2.A4@1039.75,2455.46 ; 1039.75,2429.56 ccw(c1060.56,2429.56) 1045.85,2414.85 ccw(c1059.97,2428.97) 1059.97,2409 ; U2.A4@1039.75,2431.63 cw(c1049.71,2431.63) U2.A4@1042.67,2438.67 ; v2@1044.51,2409 1143,2409 1207,2473 C34.2@1398,2473 1594.68,2473 v2(1631.69,2436) ; v2@1045.85,2401.15 cw(c1064.8,2382.2) 1064.8,2409 ; C34.2@1392.7,2467.7 ccw(c1379.89,2454.89) 1379.89,2473 ccw(c1379.89,2491.11) C34.2@1392.7,2478.3 ; C34.2@1403.3,2467.7 cw(c1416.11,2454.89) 1416.11,2473 cw(c1416.11,2491.11) C34.2@1403.3,2478.3 ; C26.2@1435.7,1402.7 cw(c1376,1343) 1460.42,1343 ; C26.2@1440.85,1400.5 cw(c1440.45,1380.53) 1460.42,1380.53 ; C26.2@1441,1400.5 cw(c1441,1382.39) 1453.8,1395.2 cw(c1466.61,1408) C26.2@1448.5,1408 ; C26.2@1446.3,1402.7 cw(c1459.11,1389.89) 1459.11,1408 cw(c1459.11,1426.11) C26.2@1446.3,1413.3 ; C26.2@1449.84,1416.84 cw(c1424.29,1391.28) 1460.42,1391.28 ; U4.3@1453.58,1283.45 ccw(c1437.04,1299.98) 1460.42,1299.98 ccw(c1483.81,1299.98) U4.3@1467.27,1283.45 ; U4.3@1460.42,1276.6 1460.42,1388.58 C26.2@1441,1408 1583,1408 1631.69,1456.68 v2(1631.69,1897) ; v2@1622,2436 ccw(c1598.62,2436) 1615.15,2452.53 ccw(c1631.69,2469.07) v2@1631.69,2445.68 ; v2@1624.84,1890.15 cw(c1608.3,1873.62) 1631.69,1873.62 cw(c1655.07,1873.62) v2@1638.53,1890.15
  Bottom Layer w8: v2@1039,2392.32 cw(c1039,2354.45) 1065.78,2381.22 cw(c1092.55,2408) v2@1054.68,2408 ; v2(1039,2408) 1086,2361 v1(1086,2295) ; v1@1081.76,2299.24 ccw(c1071.51,2309.49) 1086,2309.49 ccw(c1100.49,2309.49) v1@1090.24,2299.24
  Bottom Layer w20: v2@852,2408 v2(1039,2408) ; v2@857.85,2402.15 cw(c871.97,2388.03) 871.97,2408 ; v2@857.85,2415.85 ccw(c876.8,2434.8) 876.8,2408 ; v2@1032.15,2401.15 ccw(c1015.62,2384.62) 1015.62,2408 ccw(c1015.62,2431.38) v2@1032.15,2414.85 ; v2@1624.84,1903.85 ccw(c1608.3,1920.38) 1631.69,1920.38 ccw(c1655.07,1920.38) v2@1638.53,1903.85 ; v2@1624.84,2429.15 cw(c1608.3,2412.62) 1631.69,2412.62 cw(c1655.07,2412.62) v2@1638.53,2429.15 ; v2(1631.69,1897) v2(1631.69,2436)
VCORE: C10.1 C24.1 U1.4 | length 498.8
  Top Layer w8: C10.1@641.45,853.05 ccw(c618.41,876.09) 651,876.09 ccw(c683.59,876.09) C10.1@660.55,853.05 ; C24.1@641.45,918.45 cw(c618.41,895.41) 651,895.41 cw(c683.59,895.41) C24.1@660.55,918.45 ; C24.1@643.6,939.29 ccw(c634.6,953) 651,953 ; C10.1@651,843.5 C24.1@651,928 651,953 ; C24.1@658.4,939.29 cw(c667.4,953) 651,953 ; U1.4@865.4,1049.6 777.6,1049.6 691,963 661,963 651,953
VDD: C1.2 C3.2 JP1.2 JP5.1 P1.1 R4.2 R7.1 R14.2 U1.5 VBAT_MODE.1 | length 7806.2
  Top Layer w8: C1.2@497.42,747.21 cw(c491.16,736) 504,736 ; C1.2@510.58,747.21 ccw(c516.84,736) 504,736 ; C1.2@513.55,749.45 cw(c536.59,726.41) 536.59,759 cw(c536.59,791.59) C1.2@513.55,768.55 ; v1(547,723) 540,730 510,730 504,736 ; R7.1@576.45,1484.45 cw(c553.41,1461.41) 586,1461.41 cw(c618.59,1461.41) R7.1@595.55,1484.45 ; C3.2@581.45,749.45 ccw(c558.41,726.41) 558.41,759 ccw(c558.41,791.59) C3.2@581.45,768.55 ; C3.2@582.9,769.8 ccw(c570.75,786) 591,786 ; R7.1@586,1494 586,1461 v1(621,1426) ; C3.2@599.1,769.8 cw(c611.25,786) 591,786 ; v1@615,1426 ccw(c600.51,1426) 610.76,1436.24 ccw(c621,1446.49) v1@621,1432 ; v1@743,987 cw(c728.51,987) 738.76,976.76 cw(c749,966.51) v1@749,981 ; v1@749,993 ccw(c749,1007.49) 759.24,997.24 ccw(c769.49,987) v1@755,987 ; U1.5@865.4,1033.85 795.85,1033.85 v1(749,987) 685,923 685,824 661,800 605,800 591,786 ; R4.2@1128.45,1484.45 cw(c1105.41,1461.41) 1138,1461.41 cw(c1170.59,1461.41) R4.2@1147.55,1484.45 ; v1@1133.76,1450.24 ccw(c1123.51,1460.49) 1138,1460.49 ccw(c1152.49,1460.49) v1@1142.24,1450.24 ; v1(1138,1446) R4.2@1138,1494 ; R4.2@1138,1480.5 cw(c1138,1411.69) 1186.65,1460.35 ; R4.2@1138,1488.5 cw(c1138,1439.01) 1173,1474 ; R4.2@1138,1496.5 cw(c1138,1466.32) 1159.34,1487.66 ; R4.2@1141.67,1489.91 cw(c1149.37,1481.32) 1157.53,1489.47 ; R4.2@1146,1491 1156,1491 ; R4.2@1147.01,1483.95 cw(c1155.02,1475.02) 1163.5,1483.5 ; R4.2@1149.75,1487.36 cw(c1156,1483.82) 1156,1491 ; R4.2@1151.45,1495.17 ccw(c1156,1495.57) 1156,1491 ; 1221,1426 1156,1491 ; R14.2@1296,922.78 R14.2@1296.78,922 ; 504,736 C1.2@504,759 C3.2@591,759 591,786
  Top Layer w20: v2(990,717) 1139,717 1206,784 1206,998 1244,1036 ; v2@996.85,710.15 cw(c1013.38,693.62) 1013.38,717 cw(c1013.38,740.38) v2@996.85,723.85 ; 1221,1426 1221,1059 1244,1036 ; 1221,1428 1273,1480 v2(1273,1613) ; v2@1266.15,1606.15 cw(c1249.62,1589.62) 1273,1589.62 cw(c1296.38,1589.62) v2@1279.85,1606.15 ; R14.2@1291.48,927.3 ccw(c1278.67,940.11) 1296.78,940.11 ccw(c1314.89,940.11) R14.2@1302.08,927.3 ; R14.2@1296.78,922 1296.78,964.78 1317,985 ; JP5.1@1298.32,1017.32 ccw(c1253.22,972.22) 1253.22,1036 ccw(c1253.22,1099.78) JP5.1@1298.32,1054.68 ; JP5.1@1301.76,1014.42 cw(c1280.98,985) 1317,985 ; JP5.1@1332.24,1014.42 ccw(c1353.02,985) 1317,985 ; 1244,1036 JP5.1@1317,1036 1317,985
  Bottom Layer w8: v1(621,1426) 1118,1426 v1(1138,1446) ; v1@625.24,1421.76 cw(c635.49,1411.51) 635.49,1426 cw(c635.49,1440.49) v1@625.24,1430.24 ; v1@749,981 cw(c749,966.51) 759.24,976.76 cw(c769.49,987) v1@755,987 ; v1(749,987) 877,859 1055,859 1150,954 1224,954 1276.22,901.78 VBAT_MODE.1@1417,901.78 ; v1@1132,1446 cw(c1117.51,1446) 1127.76,1435.76 cw(c1138,1425.51) v1@1138,1440 ; v2@1272,1612 1662,1612 1708,1658 ; v2@1278.43,1618.43 ccw(c1293.97,1633.97) 1293.97,1612 ; v2@1284.09,1601.91 cw(c1308.45,1577.55) 1308.45,1612 ; v2@1284.09,1624.09 ccw(c1313.28,1653.28) 1313.28,1612 ; VBAT_MODE.1@1394.08,878.86 ccw(c1338.74,823.52) 1338.74,901.78 ccw(c1338.74,980.04) VBAT_MODE.1@1394.08,924.7 ; VBAT_MODE.1@1399.73,884.51 ccw(c1358.05,842.83) 1358.05,901.78 ccw(c1358.05,960.73) VBAT_MODE.1@1399.73,919.04 ; VBAT_MODE.1@1405.39,890.17 ccw(c1377.37,862.14) 1377.37,901.78 ccw(c1377.37,941.41) VBAT_MODE.1@1405.39,913.39 ; JP1.2@1690.62,1689.64 cw(c1670.52,1658) 1708,1658 ; JP1.2@1694.91,1696.39 cw(c1679.77,1672.56) 1708,1672.56 cw(c1736.23,1672.56) JP1.2@1721.09,1696.39 ; JP1.2@1708,1717 1708,1658 ; JP1.2@1725.38,1689.64 ccw(c1745.48,1658) 1708,1658
  Bottom Layer w20: P1.1@73,2338 439,2338 517,2260 1233,2260 1273,2220 v2(1273,1613) ; P1.1@86.81,2324.19 cw(c120.14,2290.86) 120.14,2338 cw(c120.14,2385.14) P1.1@86.81,2351.81 ; 561.49,717 cw(c561.49,737.49) v1(547,723) 553,717 v2(990,717) ; v2@983.15,710.15 ccw(c966.62,693.62) 966.62,717 ccw(c966.62,740.38) v2@983.15,723.85 ; v2@1266.15,1619.85 ccw(c1249.62,1636.38) 1273,1636.38 ccw(c1296.38,1636.38) v2@1279.85,1619.85
VDD_LINK: C20.2 C21.2 C29.2 C32.1 LED3.1 LED4.1 R6.2 R30.1 R55.1 TP6.1 U3.12 U3.13 U3.20 U3.31 | length 3899.4
  Top Layer w8: C29.2@475.45,2139.55 ccw(c452.41,2162.59) 485,2162.59 ccw(c517.59,2162.59) C29.2@494.55,2139.55 ; R6.2@475.45,2220.95 cw(c452.41,2197.91) 485,2197.91 cw(c517.59,2197.91) R6.2@494.55,2220.95 ; R6.2@475.45,2240.05 ccw(c452.41,2263.09) 485,2263.09 ccw(c517.59,2263.09) R6.2@494.55,2240.05 ; R55.1@475.45,2321.45 cw(c452.41,2298.41) 485,2298.41 cw(c517.59,2298.41) R55.1@494.55,2321.45 ; C29.2@485,2123.67 C29.2@485,2130 485,2178 ; R55.1@485,2331 R6.2@485,2230.5 485,2227.33 485,2178 ; v1@704,2073 ccw(c689.51,2073) 699.76,2083.24 ccw(c710,2093.49) v1@710,2079 ; v1@710,2067 cw(c710,2052.51) 720.24,2062.76 cw(c730.49,2073) v1@716,2073 ; U3.20@842.8,2037.48 745.52,2037.48 v1(710,2073) 605,2178 485,2178 ; U3.13@935.31,2130 935.31,2161.31 ; v1@939.5,2171.48 cw(c925.21,2171.42) 935.31,2161.31 ; v1@941.26,2167.26 cw(c908.08,2134.08) U3.12@955,2134.08 ; v1@945.48,2165.5 ccw(c945.42,2151.21) 935.31,2161.31 ; v1@945.5,2177.5 ccw(c945.5,2191.99) 955.74,2181.74 ccw(c965.99,2171.5) v1@951.5,2171.5 ; v1@946.91,2172.91 cw(c927.39,2153.39) 955,2153.39 ; U3.12@955,2130 955,2162 v1(945.5,2171.5) ; v1@989.76,1867.76 cw(c978.63,1856.63) 994.37,1856.63 U3.31@994.37,1925.28 ; v1@989.76,1876.24 ccw(c978.62,1887.38) 994.37,1887.38 ; 994.37,1854.63 1021,1828 1082,1828 1096.8,1813.2 ; 994.37,1858.41 cw(c1007.59,1858.41) v1@998.24,1867.76 ; 994.37,1885.59 ccw(c1007.59,1885.59) v1@998.24,1876.24 ; R30.1@1010.13,2323.47 ccw(c996,2313.98) 996,2331 ; R30.1@1010.13,2338.53 cw(c996,2348.02) 996,2331 ; R30.1@1030.88,2321.45 cw(c1053.92,2298.41) 1053.92,2331 cw(c1053.92,2363.59) R30.1@1030.88,2340.55 ; C20.2@1089.32,1799.24 ccw(c1080.03,1813.2) 1096.8,1813.2 ; C20.2@1104.28,1799.24 cw(c1113.57,1813.2) 1096.8,1813.2 ; C20.2@1106.35,1778.45 cw(c1129.39,1755.41) 1129.39,1788 cw(c1129.39,1820.59) C20.2@1106.35,1797.55 ; C32.1@1150.95,2321.45 ccw(c1127.91,2298.41) 1127.91,2331 ccw(c1127.91,2363.59) C32.1@1150.95,2340.55 ; C32.1@1170.05,2321.45 cw(c1193.09,2298.41) 1193.09,2331 cw(c1193.09,2363.59) C32.1@1170.05,2340.55 ; C21.2@1181.45,1778.45 ccw(c1158.41,1755.41) 1158.41,1788 ccw(c1158.41,1820.59) C21.2@1181.45,1797.55 ; C21.2@1191,1788 C20.2@1096.8,1788 1096.8,1813.2 ; LED4.1@1351.22,2323.22 ccw(c1332.44,2304.44) 1332.44,2331 ccw(c1332.44,2357.56) LED4.1@1351.22,2338.78 ; LED4.1@1358,2326 LED4.1@1359,2327 ; LED4.1@1366.78,2323.22 cw(c1385.56,2304.44) 1385.56,2331 cw(c1385.56,2357.56) LED4.1@1366.78,2338.78 ; LED3.1@1458.22,2323.22 ccw(c1439.44,2304.44) 1439.44,2331 ccw(c1439.44,2357.56) LED3.1@1458.22,2338.78 ; LED3.1@1473.78,2323.22 cw(c1492.56,2304.44) 1492.56,2331 cw(c1492.56,2357.56) LED3.1@1473.78,2338.78 ; 1739.98,2331 ccw(c1739.98,2415.98) TP6.1@1800.06,2355.89 ; 1759.29,2331 ccw(c1759.29,2396.66) TP6.1@1805.72,2350.23 ; 1771.38,2331 cw(c1771.38,2290.44) TP6.1@1800.06,2319.12 ; 1778.6,2331 ccw(c1778.6,2377.35) TP6.1@1811.38,2344.58 ; TP6.1@1818.45,2337.5 1811.94,2331 LED3.1@1466,2331 LED4.1@1359,2331 C32.1@1160.5,2331 R30.1@1021.33,2331 996,2331 ; 935.31,2161.31 v1(945.5,2171.5) ; v1(945.5,2171.5) 978,2204 978,2313 996,2331
  Bottom Layer w8: v1@705.76,2068.76 cw(c695.51,2058.51) 710,2058.51 cw(c724.49,2058.51) v1@714.24,2068.76 ; v1@710,2079 ccw(c710,2093.49) 720.24,2083.24 ccw(c730.49,2073) v1@716,2073 ; v1@941.26,2167.26 ccw(c931.02,2157.01) 931.02,2171.5 ccw(c931.02,2185.99) v1@941.26,2175.74 ; v1(945.5,2171.5) 808.5,2171.5 v1(710,2073) 710,1970 808,1872 v1(994,1872) ; v1@989.76,1867.76 ccw(c979.51,1857.51) 979.51,1872 ccw(c979.51,1886.49) v1@989.76,1876.24
VLDO: C27.2 JP5.2 R12.2 U4.2 | length 1545.1
  Top Layer w8: R12.2@1119,674.5 1194.5,674.5 1217,652 v1(1348,652) ; R12.2@1128.55,664.95 cw(c1151.59,641.91) 1151.59,674.5 cw(c1151.59,707.09) R12.2@1128.55,684.05 ; v1@1343.76,647.76 ccw(c1333.51,637.51) 1333.51,652 ccw(c1333.51,666.49) v1@1343.76,656.24 ; JP5.2@1417,1036 1463,1036 ; C27.2@1441,1151 C27.2@1445.8,1155.8 ; JP5.2@1447.53,1025.1 cw(c1463,1019.57) 1463,1036 ; JP5.2@1447.53,1046.9 ccw(c1463,1052.43) 1463,1036 ; v1@1473.76,656.24 ccw(c1463.51,666.49) 1478,666.49 ccw(c1492.49,666.49) v1@1482.24,656.24 ; v1@1478,653 1478,1021 1463,1036
  Top Layer w20: U4.2@1362,1239.2 1417.8,1239.2 1441,1216 C27.2@1441,1151 ; U4.2@1368.85,1232.35 cw(c1385.38,1215.81) 1385.38,1239.2 cw(c1385.38,1262.58) U4.2@1368.85,1246.04 ; JP5.2@1399.1,1055.43 ccw(c1311.07,1150.99) C27.2@1441,1151 ; JP5.2@1412.65,1040.72 ccw(c1353.09,1105.38) 1441,1105.38 ; JP5.2@1417,1036 1441,1060 C27.2@1441,1151 ; C27.2@1435.7,1145.7 cw(c1422.89,1132.89) 1441,1132.89 cw(c1459.11,1132.89) C27.2@1446.3,1145.7 ; C27.2@1435.7,1156.3 ccw(c1422.89,1169.11) 1441,1169.11 ccw(c1459.11,1169.11) C27.2@1446.3,1156.3
  Bottom Layer w8: v1(1348,652) v1(1478,652) ; v1@1352.24,647.76 cw(c1362.49,637.51) 1362.49,652 cw(c1362.49,666.49) v1@1352.24,656.24 ; v1@1473.76,647.76 ccw(c1463.51,637.51) 1463.51,652 ccw(c1463.51,666.49) v1@1473.76,656.24
pads on no net: U2. U2.A5 U2.A8 U2.B5 U2.B8 U3.1 U3.4 U3.8 U3.9 U3.10 U3.16 U3.27 U3.28 U3.29 U3.30
copper on no net:
  other v3: 98.43,98.43 1791.34,98.43 98.43,2657.48 1791.34,2657.48

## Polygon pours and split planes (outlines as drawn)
GND on Top Layer "Top Overlay-No Net" (solid, pour order 1000): 0.55,2754.01 1890.55,2754.01 1890.55,-1.99 0.55,-1.99 0.55,2754.01
GND on Bottom Layer "Top Overlay-No Net" (solid, pour order 1001): -0.47,2755.76 1889.53,2755.76 1889.53,-0.24 -0.47,-0.24 -0.47,2755.76

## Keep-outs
Keep-Out Layer:
  lines w5: 0,78.74 0,2677.17 cw(c78.74,2677.17) 78.74,2755.91 1811.02,2755.91 cw(c1811.02,2677.17) 1889.76,2677.17 1889.76,78.74 ; 0,80 ccw(c79.5,79.5) 79,0 ; 78.74,0 1811.02,0 ; 1811,0 ccw(c1811,79) 1890,79

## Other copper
Top Layer:
  pour cut-out: 1358,995 1359,996 1460,996 1460,953 1459,954 1358,954

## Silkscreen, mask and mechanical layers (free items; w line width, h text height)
Top Overlay:
  lines w10: 121.1,179.91 337.21,179.91 337.21,1577.47 121.1,1577.47 ; 121.1,279.74 337.21,279.74 ; 121.1,379.56 337.21,379.56 ; 121.1,479.39 337.21,479.39 ; 121.1,579.21 337.21,579.21 ; 121.1,679.04 337.21,679.04 ; 121.1,778.87 337.21,778.87 ; 121.1,878.69 337.21,878.69 ; 121.1,978.52 337.21,978.52 ; 121.1,1078.34 337.21,1078.34 ; 121.1,1178.17 337.21,1178.17 ; 121.1,1278 337.21,1278 ; 121.1,1377.82 337.21,1377.82 ; 121.1,1477.65 337.21,1477.65 ; 1547,279.83 1763.11,279.83 ; 1547,379.65 1763.11,379.65 ; 1547,479.48 1763.11,479.48 ; 1547,579.3 1763.11,579.3 ; 1547,679.13 1763.11,679.13 ; 1547,778.96 1763.11,778.96 ; 1547,878.78 1763.11,878.78 ; 1547,978.61 1763.11,978.61 ; 1547,1078.43 1763.11,1078.43 ; 1547,1178.26 1763.11,1178.26 ; 1547,1278.09 1763.11,1278.09 ; 1547,1377.91 1763.11,1377.91 ; 1547,1477.74 1763.11,1477.74 ; 1763.11,180 1547,180 1547,1577.56 1763.11,1577.56
  text "CMSIS-DAP" at 1284,2681 h51.18
  text "VCC" at 145,2313 h50
  text "GND" at 145,2212.5 h50
  text "SDIO" at 145,2112 h50
  text "SCLK" at 145,2011.5 h50
  text "NRST" at 145,1911 h50
  text "BOOT0" at 1653,1782 h50
  text "HB1023C" at 47,1775 h60
  text "LITE-32" at 74,1679 h60
  text "USER" at 1281,1596 h50
  text "PC11" at 156.21,1503.61 h51.18
  text "PC10" at 1568.11,1503.7 h51.18
  text "PB3" at 156.21,1403.61 h51.18
  text "PC9" at 1568.11,1403.7 h51.18
  text "PB4" at 156.21,1303.61 h51.18
  text "PA14" at 1568.11,1303.7 h51.18
  text "RESET" at 557,1240 h50 r90
  text "PB6" at 156.21,1203.61 h51.18
  text "PA13" at 1568.11,1203.7 h51.18
  text "PB7" at 156.21,1103.61 h51.18
  text "PA12" at 1568.11,1103.7 h51.18
  text "GND" at 156.21,1003.61 h51.18
  text "PA11" at 1568.11,1003.7 h51.18
  text "PwrTest" at 1214,954 h50 r90
  text "GND" at 156.21,903.61 h51.18
  text "PC8" at 1568.11,903.7 h51.18
  text "PA1" at 156.21,803.61 h51.18
  text "PC7" at 1568.11,803.7 h51.18
  text "PA2" at 156.21,703.61 h51.18
  text "PA9" at 1568.11,703.7 h51.18
  text "GND" at 156.21,602.61 h51.18
  text "PA8" at 1568.11,602.7 h51.18
  text "PA4" at 156.21,503.61 h51.18
  text "PB14" at 1568.11,503.7 h51.18
  text "PA0" at 156.21,403.61 h51.18
  text "PB0" at 1568.11,403.7 h51.18
  text "PF0" at 156.21,303.61 h51.18
  text "PA7" at 1568.11,303.7 h51.18
  text "PF1" at 156.21,203.61 h51.18
  text "PA6" at 1568.11,203.7 h51.18
Mechanical 1:
  lines w5: 0,78.74 0,2677.17 cw(c78.74,2677.17) 78.74,2755.91 1811.02,2755.91 ; 0,81 ccw(c79.5,79.5) 78,0 ; 78.74,0 1811.02,0 ; 1811,0 ccw(c1811,79) 1890,79 ; 1811.06,2755.91 cw(c1811.06,2677.17) 1889.8,2677.17 1889.76,78.74

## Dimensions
1811.02,2755.91 to 1811.02,0 on Mechanical 1
0,78.74 to 1889.76,78.74 on Mechanical 1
